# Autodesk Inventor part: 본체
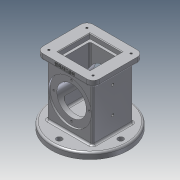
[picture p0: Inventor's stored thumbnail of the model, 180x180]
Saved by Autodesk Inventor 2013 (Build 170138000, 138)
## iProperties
Created: 2018-10
Part Number: 본체
Material: 알루미늄 6061
Document SubType Name: Modeling
Designer: Administrator
Density: 2.71 g/cm^3
Mass: 988.221 g
Surface Area: 743.905 cm^2
Volume: 364.657 cm^3
Author: Administrator
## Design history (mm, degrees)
sketch "스케치1"
  geometry: L1 (-37, 44)-(37, 44); L2 (37, 44)-(37, -44); L3 (37, -44)-(-37, -44); L4 (-37, -44)-(-37, 44); L5 (-37, 44)-(37, -44); L6 (37, 44)-(-37, -44); 1 further point
  constraints: 12 end point, 2 midpoint, 2 parallel, 1 horizontal, 1 perpendicular
  dimensions: "d0" = 74 distance of L2.end L3.end; "d1" = 88 distance of L1.end L2.end
extrude "돌출1" new body sketch "스케치1" stored distance "d2" = 66; taper "d3" = 0 deg
sketch "스케치2"
  geometry: L1 (-9, 74)-(83, 74); L2 (83, 74)-(83, -8); L3 (83, -8)-(-9, -8); L4 (-9, -8)-(-9, 74); L5 (-9, 74)-(83, -8); L6 (83, 74)-(-9, -8); 1 further point
  constraints: 12 end point, 2 midpoint, 2 parallel, 1 horizontal, 1 perpendicular
  dimensions: "d4" = 92 distance of L2.end L3.end; "d5" = 82 distance of L1.end L2.end
extrude "돌출2" join sketch "스케치2" distance "d6" = 10; taper "d7" = 0 deg
sketch "스케치3"
  geometry: C1 r 62.5 at (37, -33); 1 further point
  constraints: 1 centre point, 1 coincident
  dimensions: "d8" = 125 diameter of C1
extrude "돌출3" join sketch "스케치3" distance "d9" = 10; taper "d10" = 0 deg
sketch "스케치4"
  geometry: L1 (-62.5, -54)-(62.5, -54) reference; L2 (0, -54)-(0, 0); C1 r 35 at (0, 0)
  constraints: 2 end point, 1 centre point, 1 coincident, 1 midpoint, 1 perpendicular
  dimensions: "d11" = 54 distance of L2.start L2.end (derived); "d12" = 70 diameter of C1
extrude "돌출4" cut sketch "스케치4" distance "d13" = 3; taper "d14" = 0 deg
sketch "스케치5"
  geometry: L1 (-62.5, -54)-(62.5, -54) reference; L2 (0, -54)-(0, 0); C1 r 35 at (0, 0)
  constraints: 2 end point, 1 centre point, 1 coincident, 1 midpoint, 1 perpendicular
  dimensions: "d15" = 54 distance of L2.start L2.end (derived); "d16" = 70 diameter of C1
extrude "돌출5" cut sketch "스케치5" distance "d17" = 3; taper "d18" = 0 deg
sketch "스케치6"
  geometry: C1 r 35 at (0, 0) reference; C2 r 24 at (0, 0)
  constraints: 1 centre point, 1 coincident
  dimensions: "d19" = 48 diameter of C2
extrude "돌출6" cut sketch "스케치6" stored distance "d20" = 3; taper "d21" = 0 deg
sketch "스케치7"
  geometry: L1 (11, 59)-(63, 59); L2 (63, 59)-(63, 7); L3 (63, 7)-(11, 7); L4 (11, 7)-(11, 59); L5 (11, 59)-(63, 7); L6 (63, 59)-(11, 7); 1 further point
  constraints: 12 end point, 2 midpoint, 2 parallel, 1 horizontal, 1 perpendicular
  dimensions: "d22" = 52 distance of L2.end L3.end; "d23" = 52 distance of L1.end L2.end
extrude "돌출7" cut sketch "스케치7" distance "d24" = 8; taper "d25" = 0 deg
sketch "스케치8"
  geometry: L1 (15, 55)-(59, 55); L2 (59, 55)-(59, 11); L3 (59, 11)-(15, 11); L4 (15, 11)-(15, 55); L5 (15, 55)-(59, 11); L6 (59, 55)-(15, 11); 1 further point
  constraints: 12 end point, 2 midpoint, 2 parallel, 1 horizontal, 1 perpendicular
  dimensions: "d26" = 44 distance of L2.end L3.end; "d27" = 44 distance of L1.end L2.end
extrude "돌출8" cut sketch "스케치8" distance "d28" = 74; taper "d29" = 0 deg
sketch "스케치9"
  geometry: C1 r 62.5 at (0, 0) reference; C2 r 28 at (0, 0)
  constraints: 1 centre point, 1 coincident
  dimensions: "d30" = 56 diameter of C2
extrude "돌출9" cut sketch "스케치9" distance "d31" = 18; taper "d32" = -10 deg
sketch "스케치10"
  geometry: L1 (0, 0)-(0, 29); C1 r 35 at (0, 0) reference; 1 further point
  constraints: 2 end point, 1 coincident, 1 vertical
  dimensions: "d33" = 29 distance of L1.start L1.end
hole "구멍1" sketch "스케치10" at (0, 29) diameter "d34" = 3.242; stored, may be unused: countersink angle "d38" = 90 deg, drill point angle "d40" = 118 deg; dims "d35" = 4, "d36" = 4, "d37" = 2, "d39" = 6
sketch "스케치11"
  geometry: L1 (0, 0)-(0, 50); C1 r 62.5 at (0, 0) reference; 1 further point
  constraints: 2 end point, 1 coincident, 1 vertical
  dimensions: "d44" = 50 distance of L1.start L1.end
hole "구멍2" sketch "스케치11" at (0, 50) diameter "d45" = 9; stored, may be unused: countersink angle "d49" = 90 deg, drill point angle "d51" = 118 deg; dims "d46" = 4, "d47" = 4, "d48" = 2, "d50" = 6
sketch "스케치12"
  geometry: L1 (61, -98)-(5, -98) reference; L2 (33, -98)-(33, -61); 2 further points
  constraints: 2 end point, 1 coincident, 1 midpoint, 1 perpendicular
  dimensions: "d55" = 37 distance of L2.start L2.end
hole "구멍3" sketch "스케치12" at (33, -61) diameter "d57" = 4.134; stored, may be unused: countersink angle "d61" = 90 deg, drill point angle "d63" = 118 deg; dims "d58" = 4, "d59" = 4, "d60" = 2, "d62" = 6
sketch "스케치13"
  geometry: L1 (66, 0)-(66, -88) reference; L2 (33, -61)-(33, -18); C1 r 2.067 at (33, -61) reference; 2 further points
  constraints: 2 end point, 1 coincident, 1 parallel
  dimensions: "d64" = 43 distance of L2.start L2.end
hole "구멍4" sketch "스케치13" at (33, -18) diameter "d65" = 4.134; stored, may be unused: countersink angle "d69" = 90 deg, drill point angle "d71" = 118 deg; dims "d66" = 4, "d67" = 4, "d68" = 2, "d70" = 6
fillet "모깎기1" dims "d72" = 10
sketch "스케치14"
  geometry: A1 r 10 centre (1, 64) between (1, 74) and (-9, 64) reference; A2 r 10 centre (1, 2) between (-9, 2) and (1, -8) reference; A3 r 10 centre (73, 2) between (73, -8) and (83, 2) reference; A4 r 10 centre (73, 64) between (83, 64) and (73, 74) reference; 5 further points
  constraints: 4 coincident
hole "구멍5" sketch "스케치14" at (1, 64), (73, 64), (73, 2), (1, 2) diameter "d73" = 3.242; stored, may be unused: countersink angle "d77" = 90 deg, drill point angle "d79" = 118 deg; dims "d74" = 4, "d75" = 4, "d76" = 2, "d78" = 6
chamfer "모따기1" distance "d80" = 1; stored, may be unused: second distance "d81" = 2, angle "d82" = 45 deg
fillet "모깎기2" dims "d83" = 3
fillet "모깎기3" dims "d84" = 3
fillet "모깎기4" dims "d85" = 3
fillet "모깎기5" dims "d86" = 3
fillet "모깎기6" dims "d87" = 3
fillet "모깎기7" dims "d88" = 3
fillet "모깎기8" dims "d89" = 3
sketch "스케치15"
  geometry: L1 (0, 0)-(72, 0) reference; L2 (-10, 0)-(-10, -7) reference; 2 further points
  constraints: 1 other
  dimensions: "d90" = 46 distance from line of L2 point (36, -4); "d91" = 4 distance from line of point (36, -4) L1
feature "엠보싱1" sketch "스케치15" dims "d0" = 74, "d1" = 88, "d9" = 10, "d92" = 0.5, "d93" = 0
fillet "모깎기9" dims "d94" = 3
node "솔리드1"
pattern_circular "원형 패턴1" dims angle "d42" = 360 deg
mirror "대칭1"
pattern_circular "원형 패턴2" dims angle "d53" = 360 deg
